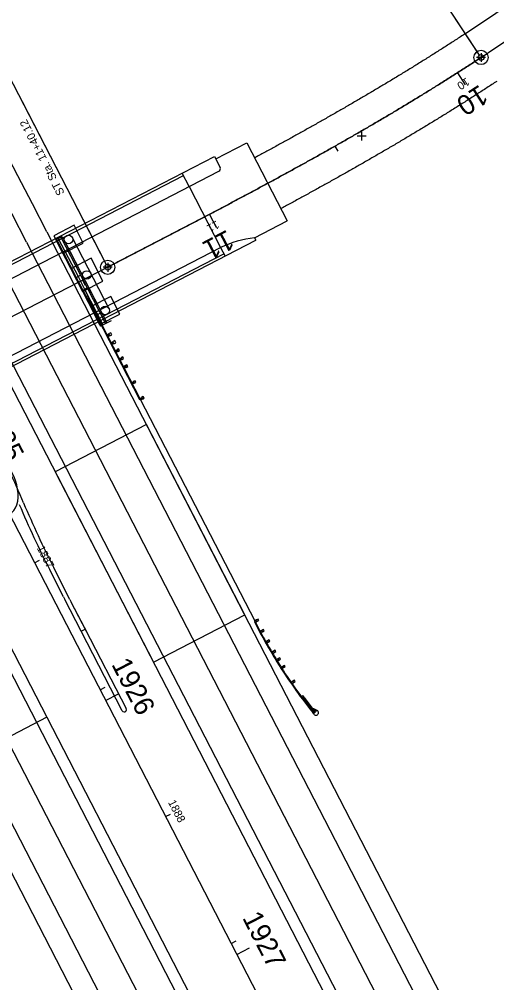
# Model space of a CAD drawing. Extents: x 6334 to 41599, y 9030 to 59113.
# Drawn here: x 24336.9 to 24504.1, y 28201.4 to 28538.5 of the extents above; entities that cross this region are included whole.
import ezdxf

# ---------------------------------------------------------------- set-up
doc = ezdxf.new("R2010")
doc.units = 0
for name, color, linetype in [('BR_X_Gen_Approach_Slab', 7, 'Continuous'), ('BR_X_Rail_Object', 7, 'Continuous'), ('BR_X_SV_Pier', 7, 'Continuous'), ('GE_X_CL_20', 7, 'Continuous'), ('GE_X_CL_50', 7, 'Continuous'), ('GK_Visualization', 7, 'Continuous'), ('MT_P_Edge_Line', 7, 'Continuous'), ('PM_X_Lane_Line', 7, 'Continuous'), ('PV_X_EOP', 7, 'Continuous'), ('PV_X_Shoulder', 7, 'Continuous'), ('RD_P_Concrete_Barrier', 7, 'Continuous'), ('RD_P_GR_Lt', 7, 'Continuous'), ('RD_P_GR_Lt_Replaced', 7, 'Continuous'), ('RD_P_GR_Rt', 7, 'Continuous'), ('RD_P_GR_Rt_Replaced', 7, 'Continuous'), ('RD_X_GR_Lt', 7, 'Continuous')]:
    doc.layers.add(name, color=color, linetype=linetype)

msp = doc.modelspace()

# ---------------------------------------------------------------- linework, layer by layer
at = {"layer": 'BR_X_Gen_Approach_Slab'}
for p, q in [((24405.7, 28489.66), (24416.6, 28495.29)), ((24416.6, 28495.29), (24430.71, 28467.98)), ((24396.38, 28479.97), (24407.39, 28458.65)), ((24419.25, 28462.06), (24430.71, 28467.98))]:
    msp.add_line(p, q, dxfattribs=at)
at = {"layer": 'BR_X_Rail_Object'}
for p, q in [((24189.83, 28379.27), (24405.24, 28490.55)), ((24405.24, 28490.55), (24407.23, 28486.7)), ((24193.16, 28374.99), (24406.8, 28485.35)), ((24201.6, 28384.22), (24394.39, 28483.82)), ((24396.38, 28479.97), (24393.93, 28484.71)), ((24419.25, 28462.06), (24419.71, 28461.17)), ((24205.41, 28350.46), (24419.71, 28461.17)), ((24214.6, 28359.05), (24407.39, 28458.65)), ((24407.39, 28458.65), (24408.96, 28455.61)), ((24215.71, 28356.9), (24408.5, 28456.5))]:
    msp.add_line(p, q, dxfattribs=at)
for centre, radius, start, end in [((24406.34, 28486.24), 1, 297.3208, 27.3208), ((24423.7, 28424.26), 38.06, 96.701, 115.3649)]:
    msp.add_arc(centre, radius, start, end, dxfattribs=at)
at = {"layer": 'BR_X_SV_Pier'}
for p, q in [((24356.1, 28466.43), (24348.99, 28462.76)), ((24359.31, 28460.21), (24356.1, 28466.43)), ((24348.99, 28462.76), (24352.2, 28456.54)), ((24355.48, 28462.18), (24368.33, 28437.3)), ((24352.2, 28456.54), (24359.31, 28460.21)), ((24352.82, 28460.8), (24365.67, 28435.92)), ((24362.06, 28454.88), (24354.96, 28451.21)), ((24366.19, 28446.89), (24362.06, 28454.88)), ((24354.96, 28451.21), (24359.09, 28443.21)), ((24359.09, 28443.21), (24366.19, 28446.89)), ((24368.95, 28441.56), (24361.84, 28437.88)), ((24372.16, 28435.34), (24368.95, 28441.56)), ((24361.84, 28437.88), (24365.05, 28431.66)), ((24365.05, 28431.66), (24372.16, 28435.34))]:
    msp.add_line(p, q, dxfattribs=at)
for centre in [(24354.15, 28461.49), (24360.58, 28449.05), (24367, 28436.61)]:
    msp.add_circle(centre, 1.5, dxfattribs=at)
at = {"layer": 'GE_X_CL_20'}
for p, q in [((24498.05, 28526), (24462.96, 28579.38)), ((24490.31, 28519.79), (24491.38, 28518.11)), ((24367.42, 28452.63), (24338, 28509.58)), ((24447.42, 28494.11), (24448.4, 28492.37)), ((24403.48, 28470.25), (24404.41, 28468.48)), ((24367.88, 28451.74), (23024.38, 27757.69)), ((24359.1, 28447.21), (24360.02, 28445.43)), ((24295.92, 28438.03), (26722.77, 23740.28)), ((24342.25, 28348.35), (24344.03, 28349.27)), ((24365.2, 28303.93), (24366.97, 28304.84)), ((24388.15, 28259.5), (24389.92, 28260.42)), ((24411.1, 28215.08), (24412.87, 28216))]:
    msp.add_line(p, q, dxfattribs=at)
for centre in [(24498.6, 28525.16), (24367.88, 28451.74)]:
    msp.add_circle(centre, 1, dxfattribs=at)
msp.add_arc((24105.17, 29123.62), 716.2, 303.32083, 318.10417, dxfattribs=at)
msp.add_spline([(24367.88, 28451.74), (24369.68, 28452.67), (24371.48, 28453.6), (24373.28, 28454.53), (24375.08, 28455.46), (24376.88, 28456.4), (24378.68, 28457.33), (24380.48, 28458.26), (24382.28, 28459.19), (24384.08, 28460.12), (24385.88, 28461.06), (24387.68, 28461.99), (24389.48, 28462.93), (24391.28, 28463.86), (24393.07, 28464.8), (24394.87, 28465.74), (24396.67, 28466.67), (24398.46, 28467.61), (24400.26, 28468.56), (24402.05, 28469.5), (24403.85, 28470.44), (24405.64, 28471.39), (24407.43, 28472.33), (24409.23, 28473.28), (24411.02, 28474.23), (24412.81, 28475.18), (24414.6, 28476.13), (24416.38, 28477.09), (24418.17, 28478.04), (24419.96, 28479), (24421.74, 28479.96), (24423.53, 28480.92), (24425.31, 28481.89), (24427.09, 28482.85), (24428.87, 28483.82), (24430.65, 28484.79), (24432.43, 28485.77), (24434.21, 28486.74), (24435.98, 28487.72), (24437.76, 28488.7), (24439.53, 28489.69), (24441.3, 28490.67), (24443.07, 28491.66), (24444.84, 28492.65), (24446.6, 28493.65), (24448.37, 28494.65), (24450.13, 28495.65), (24451.89, 28496.65), (24453.65, 28497.66), (24455.41, 28498.67), (24457.16, 28499.68), (24458.91, 28500.7), (24460.67, 28501.72), (24462.42, 28502.75), (24464.16, 28503.77), (24465.91, 28504.8), (24467.65, 28505.84), (24469.39, 28506.88), (24471.13, 28507.92), (24472.87, 28508.97), (24474.6, 28510.02), (24476.33, 28511.07), (24478.06, 28512.13), (24479.79, 28513.19), (24481.51, 28514.26), (24483.23, 28515.33), (24484.95, 28516.4), (24486.67, 28517.48), (24488.38, 28518.56), (24490.09, 28519.65), (24491.8, 28520.74), (24493.5, 28521.84), (24495.2, 28522.94), (24496.9, 28524.05), (24498.6, 28525.16)], degree=3, dxfattribs=at)
at = {"layer": 'GE_X_CL_50'}
for p, q in [((24497.22, 28527.25), (24409.49, 28660.7)), ((24366.73, 28453.96), (24293.18, 28596.34)), ((24490.31, 28519.79), (24493, 28515.58)), ((24403.48, 28470.25), (24405.81, 28465.82)), ((24367.88, 28451.74), (23024.38, 27757.69)), ((24295.92, 28438.03), (26722.77, 23740.28)), ((24367.16, 28300.13), (24371.6, 28302.43)), ((24413.06, 28211.29), (24417.5, 28213.58))]:
    msp.add_line(p, q, dxfattribs=at)
for centre in [(24498.6, 28525.16), (24367.88, 28451.74)]:
    msp.add_circle(centre, 2.5, dxfattribs=at)
msp.add_arc((24105.17, 29123.62), 716.2, 303.32083, 318.10417, dxfattribs=at)
msp.add_spline([(24498.6, 28525.16), (24496.9, 28524.05), (24495.2, 28522.94), (24493.5, 28521.84), (24491.8, 28520.74), (24490.09, 28519.65), (24488.38, 28518.56), (24486.67, 28517.48), (24484.95, 28516.4), (24483.23, 28515.33), (24481.51, 28514.26), (24479.79, 28513.19), (24478.06, 28512.13), (24476.33, 28511.07), (24474.6, 28510.02), (24472.87, 28508.97), (24471.13, 28507.92), (24469.39, 28506.88), (24467.65, 28505.84), (24465.91, 28504.8), (24464.16, 28503.77), (24462.42, 28502.75), (24460.67, 28501.72), (24458.91, 28500.7), (24457.16, 28499.68), (24455.41, 28498.67), (24453.65, 28497.66), (24451.89, 28496.65), (24450.13, 28495.65), (24448.37, 28494.65), (24446.6, 28493.65), (24444.84, 28492.65), (24443.07, 28491.66), (24441.3, 28490.67), (24439.53, 28489.69), (24437.76, 28488.7), (24435.98, 28487.72), (24434.21, 28486.74), (24432.43, 28485.77), (24430.65, 28484.79), (24428.87, 28483.82), (24427.09, 28482.85), (24425.31, 28481.89), (24423.53, 28480.92), (24421.74, 28479.96), (24419.96, 28479), (24418.17, 28478.04), (24416.38, 28477.09), (24414.6, 28476.13), (24412.81, 28475.18), (24411.02, 28474.23), (24409.23, 28473.28), (24407.43, 28472.33), (24405.64, 28471.39), (24403.85, 28470.44), (24402.05, 28469.5), (24400.26, 28468.56), (24398.46, 28467.61), (24396.67, 28466.67), (24394.87, 28465.74), (24393.07, 28464.8), (24391.28, 28463.86), (24389.48, 28462.93), (24387.68, 28461.99), (24385.88, 28461.06), (24384.08, 28460.12), (24382.28, 28459.19), (24380.48, 28458.26), (24378.68, 28457.33), (24376.88, 28456.4), (24375.08, 28455.46), (24373.28, 28454.53), (24371.48, 28453.6), (24369.68, 28452.67), (24367.88, 28451.74)], degree=3, dxfattribs=at)
at = {"layer": 'GK_Visualization'}
for p, q in [((24498.6, 28526.72), (24498.6, 28523.6)), ((24498.6, 28526.72), (24498.6, 28523.6)), ((24500.16, 28525.16), (24497.04, 28525.16)), ((24500.16, 28525.16), (24497.04, 28525.16)), ((24456.77, 28499.23), (24456.77, 28496.11)), ((24458.33, 28497.67), (24455.21, 28497.67)), ((24367.88, 28451.74), (23024.38, 27757.69)), ((24369.44, 28451.74), (24366.32, 28451.74)), ((24367.88, 28453.3), (24367.88, 28450.18)), ((24295.92, 28438.03), (26722.77, 23740.28)), ((24295.92, 28438.03), (26722.77, 23740.28))]:
    msp.add_line(p, q, dxfattribs=at)
msp.add_arc((24105.17, 29123.62), 716.2, 303.32083, 318.10417, dxfattribs=at)
msp.add_arc((24105.17, 29123.62), 716.2, 303.32083, 318.10417, dxfattribs=at)
msp.add_spline([(24498.6, 28525.16), (24496.9, 28524.05), (24495.2, 28522.94), (24493.5, 28521.84), (24491.8, 28520.74), (24490.09, 28519.65), (24488.38, 28518.56), (24486.67, 28517.48), (24484.95, 28516.4), (24483.23, 28515.33), (24481.51, 28514.26), (24479.79, 28513.19), (24478.06, 28512.13), (24476.33, 28511.07), (24474.6, 28510.02), (24472.87, 28508.97), (24471.13, 28507.92), (24469.39, 28506.88), (24467.65, 28505.84), (24465.91, 28504.8), (24464.16, 28503.77), (24462.42, 28502.75), (24460.67, 28501.72), (24458.91, 28500.7), (24457.16, 28499.68), (24455.41, 28498.67), (24453.65, 28497.66), (24451.89, 28496.65), (24450.13, 28495.65), (24448.37, 28494.65), (24446.6, 28493.65), (24444.84, 28492.65), (24443.07, 28491.66), (24441.3, 28490.67), (24439.53, 28489.69), (24437.76, 28488.7), (24435.98, 28487.72), (24434.21, 28486.74), (24432.43, 28485.77), (24430.65, 28484.79), (24428.87, 28483.82), (24427.09, 28482.85), (24425.31, 28481.89), (24423.53, 28480.92), (24421.74, 28479.96), (24419.96, 28479), (24418.17, 28478.04), (24416.38, 28477.09), (24414.6, 28476.13), (24412.81, 28475.18), (24411.02, 28474.23), (24409.23, 28473.28), (24407.43, 28472.33), (24405.64, 28471.39), (24403.85, 28470.44), (24402.05, 28469.5), (24400.26, 28468.56), (24398.46, 28467.61), (24396.67, 28466.67), (24394.87, 28465.74), (24393.07, 28464.8), (24391.28, 28463.86), (24389.48, 28462.93), (24387.68, 28461.99), (24385.88, 28461.06), (24384.08, 28460.12), (24382.28, 28459.19), (24380.48, 28458.26), (24378.68, 28457.33), (24376.88, 28456.4), (24375.08, 28455.46), (24373.28, 28454.53), (24371.48, 28453.6), (24369.68, 28452.67), (24367.88, 28451.74)], degree=3, dxfattribs=at)
msp.add_spline([(24498.6, 28525.16), (24496.9, 28524.05), (24495.2, 28522.94), (24493.5, 28521.84), (24491.8, 28520.74), (24490.09, 28519.65), (24488.38, 28518.56), (24486.67, 28517.48), (24484.95, 28516.4), (24483.23, 28515.33), (24481.51, 28514.26), (24479.79, 28513.19), (24478.06, 28512.13), (24476.33, 28511.07), (24474.6, 28510.02), (24472.87, 28508.97), (24471.13, 28507.92), (24469.39, 28506.88), (24467.65, 28505.84), (24465.91, 28504.8), (24464.16, 28503.77), (24462.42, 28502.75), (24460.67, 28501.72), (24458.91, 28500.7), (24457.16, 28499.68), (24455.41, 28498.67), (24453.65, 28497.66), (24451.89, 28496.65), (24450.13, 28495.65), (24448.37, 28494.65), (24446.6, 28493.65), (24444.84, 28492.65), (24443.07, 28491.66), (24441.3, 28490.67), (24439.53, 28489.69), (24437.76, 28488.7), (24435.98, 28487.72), (24434.21, 28486.74), (24432.43, 28485.77), (24430.65, 28484.79), (24428.87, 28483.82), (24427.09, 28482.85), (24425.31, 28481.89), (24423.53, 28480.92), (24421.74, 28479.96), (24419.96, 28479), (24418.17, 28478.04), (24416.38, 28477.09), (24414.6, 28476.13), (24412.81, 28475.18), (24411.02, 28474.23), (24409.23, 28473.28), (24407.43, 28472.33), (24405.64, 28471.39), (24403.85, 28470.44), (24402.05, 28469.5), (24400.26, 28468.56), (24398.46, 28467.61), (24396.67, 28466.67), (24394.87, 28465.74), (24393.07, 28464.8), (24391.28, 28463.86), (24389.48, 28462.93), (24387.68, 28461.99), (24385.88, 28461.06), (24384.08, 28460.12), (24382.28, 28459.19), (24380.48, 28458.26), (24378.68, 28457.33), (24376.88, 28456.4), (24375.08, 28455.46), (24373.28, 28454.53), (24371.48, 28453.6), (24369.68, 28452.67), (24367.88, 28451.74)], degree=3, dxfattribs=at)
at = {"layer": 'MT_P_Edge_Line'}
for p, q in [((24381.42, 28396.72), (24349.43, 28380.2)), ((24415.84, 28330.09), (24381.42, 28396.72)), ((24349.43, 28380.2), (24383.86, 28313.57)), ((24312.12, 28360.92), (24346.54, 28294.29)), ((24383.86, 28313.57), (24415.84, 28330.09)), ((24346.54, 28294.29), (24314.56, 28277.77))]:
    msp.add_line(p, q, dxfattribs=at)
at = {"layer": 'PM_X_Lane_Line'}
for p, q in [((24328.8, 28455.01), (26755.65, 23757.26)), ((24263.05, 28421.04), (26689.9, 23723.3))]:
    msp.add_line(p, q, dxfattribs=at)
at = {"layer": 'PV_X_EOP'}
for p, q in [((24339.46, 28460.52), (26766.31, 23762.77)), ((24318.13, 28449.5), (26744.98, 23751.75)), ((24273.71, 28426.55), (26700.56, 23728.81)), ((24252.39, 28415.54), (26679.24, 23717.79))]:
    msp.add_line(p, q, dxfattribs=at)
for centre, radius, start, end in [((11569.81, 21863.73), 14372.94, 27.320833, 30.120833), ((24105.17, 29123.62), 706.2, 303.32083, 318.10417)]:
    msp.add_arc(centre, radius, start, end, dxfattribs=at)
for points in [[(24493.12, 28533.52), (24491.43, 28532.42), (24489.76, 28531.33), (24488.08, 28530.24), (24486.4, 28529.16), (24484.71, 28528.08), (24483.02, 28527.01), (24481.33, 28525.94), (24479.64, 28524.87), (24477.94, 28523.81), (24476.24, 28522.75), (24474.54, 28521.7), (24472.83, 28520.65), (24471.12, 28519.61), (24469.41, 28518.56), (24467.7, 28517.52), (24465.98, 28516.49), (24464.26, 28515.46), (24462.54, 28514.43), (24460.81, 28513.41), (24459.09, 28512.39), (24457.36, 28511.37), (24455.62, 28510.36), (24453.89, 28509.35), (24452.15, 28508.34), (24450.41, 28507.33), (24448.67, 28506.33), (24446.93, 28505.34), (24445.18, 28504.34), (24443.44, 28503.35), (24441.69, 28502.36), (24439.93, 28501.37), (24438.18, 28500.39), (24436.43, 28499.41), (24434.67, 28498.43), (24432.91, 28497.45), (24431.15, 28496.48), (24429.39, 28495.51), (24427.62, 28494.54), (24425.86, 28493.57), (24424.09, 28492.6), (24422.32, 28491.64), (24420.55, 28490.68), (24419.32, 28490.02)], [(24504.08, 28516.8), (24502.37, 28515.68), (24500.65, 28514.56), (24498.93, 28513.44), (24497.2, 28512.33), (24495.47, 28511.22), (24493.74, 28510.12), (24492, 28509.02), (24490.26, 28507.93), (24488.52, 28506.84), (24486.78, 28505.76), (24485.04, 28504.68), (24483.29, 28503.6), (24481.54, 28502.53), (24479.79, 28501.47), (24478.04, 28500.41), (24476.28, 28499.35), (24474.52, 28498.29), (24472.77, 28497.25), (24471, 28496.2), (24469.24, 28495.16), (24467.48, 28494.12), (24465.71, 28493.09), (24463.94, 28492.06), (24462.17, 28491.03), (24460.4, 28490.01), (24458.63, 28488.99), (24456.85, 28487.97), (24455.07, 28486.96), (24453.3, 28485.95), (24451.52, 28484.94), (24449.74, 28483.94), (24447.95, 28482.94), (24446.17, 28481.94), (24444.39, 28480.95), (24442.6, 28479.96), (24440.81, 28478.97), (24439.03, 28477.98), (24437.24, 28477), (24435.45, 28476.02), (24433.66, 28475.04), (24431.87, 28474.07), (24430.07, 28473.1), (24428.51, 28472.25)]]:
    msp.add_spline(points, degree=3, dxfattribs=at)
at = {"layer": 'PV_X_Shoulder'}
for p, q in [((24346.56, 28464.19), (25050.36, 27101.82)), ((24314.58, 28447.66), (25018.38, 27085.3)), ((24277.26, 28428.39), (24981.06, 27066.02)), ((24245.28, 28411.86), (24949.08, 27049.5))]:
    msp.add_line(p, q, dxfattribs=at)
msp.add_arc((11569.81, 21863.73), 14380.94, 27.320833, 30.120833, dxfattribs=at)
at = {"layer": 'RD_P_Concrete_Barrier'}
for p, q in [((24350, 28461.53), (24351.48, 28462.3)), ((24350.59, 28461.84), (24357.48, 28448.51)), ((24351.48, 28462.3), (24351.92, 28462.53)), ((24351.48, 28462.3), (24358.36, 28448.97)), ((24351.92, 28462.53), (24358.81, 28449.2)), ((24350, 28461.53), (24349.7, 28461.38)), ((24349.7, 28461.38), (24356.59, 28448.05)), ((24350, 28461.53), (24356.88, 28448.2)), ((24356.88, 28448.2), (24358.36, 28448.97)), ((24357.48, 28448.51), (24359.77, 28444.07)), ((24358.36, 28448.97), (24360.66, 28444.53)), ((24358.81, 28449.2), (24361.1, 28444.76)), ((24356.59, 28448.05), (24358.88, 28443.61)), ((24356.88, 28448.2), (24359.18, 28443.76)), ((24358.88, 28443.61), (24365.31, 28431.17)), ((24359.18, 28443.76), (24360.66, 28444.53)), ((24359.18, 28443.76), (24365.6, 28431.32)), ((24364.07, 28435.03), (24359.18, 28443.76)), ((24359.77, 28444.07), (24366.2, 28431.63)), ((24359.77, 28444.07), (24364.07, 28435.03)), ((24360.66, 28444.53), (24367.09, 28432.09)), ((24361.1, 28444.76), (24367.53, 28432.32)), ((24363.77, 28434.88), (24365.25, 28435.64)), ((24364.07, 28435.03), (24365.3, 28432.65)), ((24366.2, 28431.63), (24365.3, 28432.65)), ((24365.6, 28431.32), (24367.09, 28432.09)), ((24367.09, 28432.09), (24367.53, 28432.32)), ((24365.6, 28431.32), (24365.31, 28431.17))]:
    msp.add_line(p, q, dxfattribs=at)
at = {"layer": 'RD_P_GR_Lt'}
for p, q in [((24354.67, 28335.47), (24348.99, 28346.6)), ((24360.42, 28324.33), (24355.13, 28334.56))]:
    msp.add_line(p, q, dxfattribs=at)
for centre, start, end in [((24017.86, 28233.83), 22.9054, 27.0249), ((24658.98, 28504.76), 202.9108, 207.0303)]:
    msp.add_arc(centre, 348.01, start, end, dxfattribs=at)
at = {"layer": 'RD_P_GR_Lt_Replaced'}
for p, q in [((24379.28, 28405.58), (24419.46, 28327.81)), ((24352.39, 28336.39), (24347.57, 28345.83))]:
    msp.add_line(p, q, dxfattribs=at)
msp.add_arc((24660.51, 28505.49), 351.31, 202.9108, 207.0303, dxfattribs=at)
at = {"layer": 'RD_P_GR_Rt'}
for p, q in [((24358.59, 28324.38), (24360.02, 28325.1)), ((24372.95, 28296.58), (24358.59, 28324.38)), ((24360.02, 28325.1), (24374.38, 28297.29))]:
    msp.add_line(p, q, dxfattribs=at)
msp.add_arc((24373.67, 28296.93), 0.798, 206.5253, 26.5253, dxfattribs=at)
at = {"layer": 'RD_P_GR_Rt_Replaced'}
for p, q in [((24364.04, 28435.02), (24364.07, 28435.03)), ((24364.04, 28435.02), (24364.15, 28434.79)), ((24364.07, 28435.03), (24379.28, 28405.58)), ((24364.2, 28434.23), (24379.06, 28405.47)), ((24364.44, 28433.77), (24364.66, 28433.88)), ((24364.72, 28433.23), (24364.94, 28433.35)), ((24364.99, 28432.7), (24365.21, 28432.82)), ((24365.9, 28431.48), (24369.18, 28433.17)), ((24368.28, 28428.32), (24367.92, 28427.57)), ((24368.51, 28427.88), (24367.69, 28428.02)), ((24369.95, 28425.1), (24369.13, 28425.24)), ((24369.72, 28425.55), (24369.36, 28424.8)), ((24370.18, 28422.66), (24370.4, 28422.78)), ((24370.45, 28422.13), (24370.68, 28422.24)), ((24371.38, 28422.33), (24370.56, 28422.46)), ((24370.73, 28421.59), (24370.95, 28421.71)), ((24371.15, 28422.77), (24370.79, 28422.02)), ((24372.82, 28419.55), (24371.99, 28419.69)), ((24372.59, 28419.99), (24372.22, 28419.24)), ((24373.05, 28417.11), (24373.27, 28417.22)), ((24373.32, 28416.58), (24373.54, 28416.69)), ((24374.25, 28416.77), (24373.43, 28416.91)), ((24373.6, 28416.04), (24373.82, 28416.16)), ((24374.02, 28417.22), (24373.66, 28416.47)), ((24377.12, 28411.22), (24376.3, 28411.36)), ((24376.89, 28411.67), (24376.53, 28410.92)), ((24379.06, 28405.47), (24379.28, 28405.58)), ((24379.99, 28405.67), (24379.17, 28405.81)), ((24379.4, 28405.36), (24379.76, 28406.11)), ((24358.59, 28324.38), (24352.85, 28335.49)), ((24360.87, 28323.46), (24355.13, 28334.56)), ((24419.24, 28327.69), (24419.46, 28327.81)), ((24419.24, 28327.69), (24421.15, 28323.99)), ((24419.46, 28327.81), (24421.37, 28324.1)), ((24436.25, 28300.92), (24439.72, 28296.4)), ((24436.63, 28301.2), (24440.08, 28296.69)), ((24436.75, 28300.2), (24436.69, 28300.16)), ((24440.33, 28295.95), (24436.69, 28300.16)), ((24440.39, 28295.99), (24436.75, 28300.2)), ((24441.18, 28296.66), (24438.35, 28297.99)), ((24441.01, 28296.46), (24438.69, 28297.55)), ((24440.12, 28295.33), (24439.65, 28295.92)), ((24440.39, 28295.99), (24440.33, 28295.95)), ((24441.01, 28296.46), (24441.25, 28296.62))]:
    msp.add_line(p, q, dxfattribs=at)
for points in [[(24368.51, 28427.88), (24368.28, 28428.32), (24367.69, 28428.02), (24367.92, 28427.57)], [(24369.33, 28428.11), (24368.95, 28428.85), (24368.21, 28428.47), (24368.59, 28427.73)], [(24369.95, 28425.1), (24369.72, 28425.55), (24369.13, 28425.24), (24369.36, 28424.8)], [(24370.76, 28425.34), (24370.38, 28426.08), (24369.64, 28425.7), (24370.02, 28424.96)], [(24371.38, 28422.33), (24371.15, 28422.77), (24370.56, 28422.46), (24370.79, 28422.02)], [(24372.01, 28422.56), (24371.71, 28423.15), (24371.11, 28422.84), (24371.42, 28422.25)], [(24372.82, 28419.55), (24372.59, 28419.99), (24371.99, 28419.69), (24372.22, 28419.24)], [(24373.45, 28419.78), (24373.14, 28420.37), (24372.55, 28420.07), (24372.85, 28419.48)], [(24374.25, 28416.77), (24374.02, 28417.22), (24373.43, 28416.91), (24373.66, 28416.47)], [(24374.88, 28417.01), (24374.58, 28417.6), (24373.98, 28417.29), (24374.29, 28416.7)], [(24377.12, 28411.22), (24376.89, 28411.67), (24376.3, 28411.36), (24376.53, 28410.92)], [(24377.75, 28411.45), (24377.44, 28412.05), (24376.85, 28411.74), (24377.16, 28411.15)], [(24379.99, 28405.67), (24379.76, 28406.11), (24379.17, 28405.81), (24379.4, 28405.36)], [(24380.61, 28405.91), (24380.31, 28406.5), (24379.72, 28406.19), (24380.02, 28405.6)], [(24420.17, 28327.88), (24419.95, 28328.33), (24419.35, 28328.03), (24419.57, 28327.58)], [(24420.77, 28328.18), (24420.54, 28328.63), (24419.95, 28328.33), (24420.17, 28327.88)], [(24422.08, 28324.19), (24421.85, 28324.63), (24421.26, 28324.33), (24421.49, 28323.88)], [(24422.67, 28324.49), (24422.44, 28324.94), (24421.85, 28324.63), (24422.08, 28324.19)], [(24424.08, 28320.56), (24423.83, 28320.99), (24423.25, 28320.66), (24423.5, 28320.23)], [(24424.66, 28320.89), (24424.41, 28321.32), (24423.83, 28320.99), (24424.08, 28320.56)], [(24426.21, 28316.99), (24425.95, 28317.41), (24425.38, 28317.07), (24425.64, 28316.64)], [(24426.78, 28317.33), (24426.52, 28317.76), (24425.95, 28317.41), (24426.21, 28316.99)], [(24427.81, 28314.29), (24427.55, 28314.72), (24426.98, 28314.38), (24427.24, 28313.95)], [(24428.38, 28314.64), (24428.12, 28315.07), (24427.55, 28314.72), (24427.81, 28314.29)], [(24429.46, 28311.64), (24429.19, 28312.06), (24428.63, 28311.7), (24428.89, 28311.28)], [(24430.02, 28312), (24429.75, 28312.42), (24429.19, 28312.06), (24429.46, 28311.64)], [(24432.97, 28306.44), (24432.68, 28306.85), (24432.13, 28306.47), (24432.42, 28306.06)], [(24433.51, 28306.82), (24433.23, 28307.23), (24432.68, 28306.85), (24432.97, 28306.44)], [(24436.71, 28301.26), (24436.31, 28301.79), (24435.77, 28301.39), (24436.17, 28300.86)], [(24437.7, 28299.14), (24437.52, 28299.01), (24436.69, 28300.08), (24436.87, 28300.22)], [(24438.14, 28298.5), (24438.02, 28298.4), (24437.57, 28298.98), (24437.69, 28299.08)], [(24440.58, 28296.23), (24440.16, 28296.75), (24439.64, 28296.34), (24440.05, 28295.82)]]:
    msp.add_lwpolyline(points, close=True, dxfattribs=at)
for centre, radius, start, end in [((24364.8, 28434.57), 0.684, 160.5293, 209.272), ((24663.49, 28495.98), 349.64, 207.1573, 207.3242), ((24665.76, 28495.06), 349.64, 207.1573, 207.3242), ((24524.38, 28378.11), 116.55, 207.6678, 211.7803), ((24524.38, 28378.11), 116.3, 207.6678, 211.7803), ((24567.67, 28399.31), 164.59, 210.1142, 212.3003), ((24567.67, 28399.31), 164.34, 210.1142, 212.3003), ((24598.5, 28421.88), 202.73, 213.036, 218.4112), ((24598.5, 28421.88), 202.48, 213.036, 218.4112), ((24440.81, 28295.87), 0.875, 218.326, 64.8959)]:
    msp.add_arc(centre, radius, start, end, dxfattribs=at)
for centre in [(24364.6, 28433.72), (24365.04, 28432.88), (24370.34, 28422.62), (24370.77, 28421.77), (24373.2, 28417.06), (24373.64, 28416.22)]:
    msp.add_ellipse(centre, major_axis=(-0.0174, 0.0336), ratio=0.460352, dxfattribs=at)
at = {"layer": 'RD_X_GR_Lt'}
msp.add_ellipse((24327.54, 28376.57), major_axis=(5.97, -11.22), ratio=0.597096, start_param=4.712389, end_param=7.853982, dxfattribs=at)

# ---------------------------------------------------------------- texts
at = {"layer": 'GE_X_CL_20'}
for s, rotation, p in [('10', 212.5567, (24493.42, 28518.22)), ('ST Sta. 11+40.12', 117.3208, (24352.86, 28477.75)), ('11', 207.7501, (24405.98, 28468.17)), ('1887', 297.3208, (24342.98, 28353.48)), ('1888', 297.3208, (24388.93, 28264.52))]:
    msp.add_text(s, height=2.8, rotation=rotation, dxfattribs=at).set_placement(p)
at = {"layer": 'GE_X_CL_50'}
for s, rotation, p in [('10', 212.5567, (24498.08, 28515.86)), ('11', 207.7501, (24409.72, 28465.06)), ('1925', 297.3208, (24323.16, 28401.65)), ('1926', 297.3208, (24369.04, 28312.83)), ('1927', 297.3208, (24414.88, 28224.1))]:
    msp.add_text(s, height=7, rotation=rotation, dxfattribs=at).set_placement(p)
at = {"layer": 'RD_P_GR_Rt_Replaced'}
msp.add_text('end of barrier', height=0.25, rotation=207.3208, dxfattribs=at).set_placement((24369.08, 28433.02))

doc.saveas('drawing.dxf')
